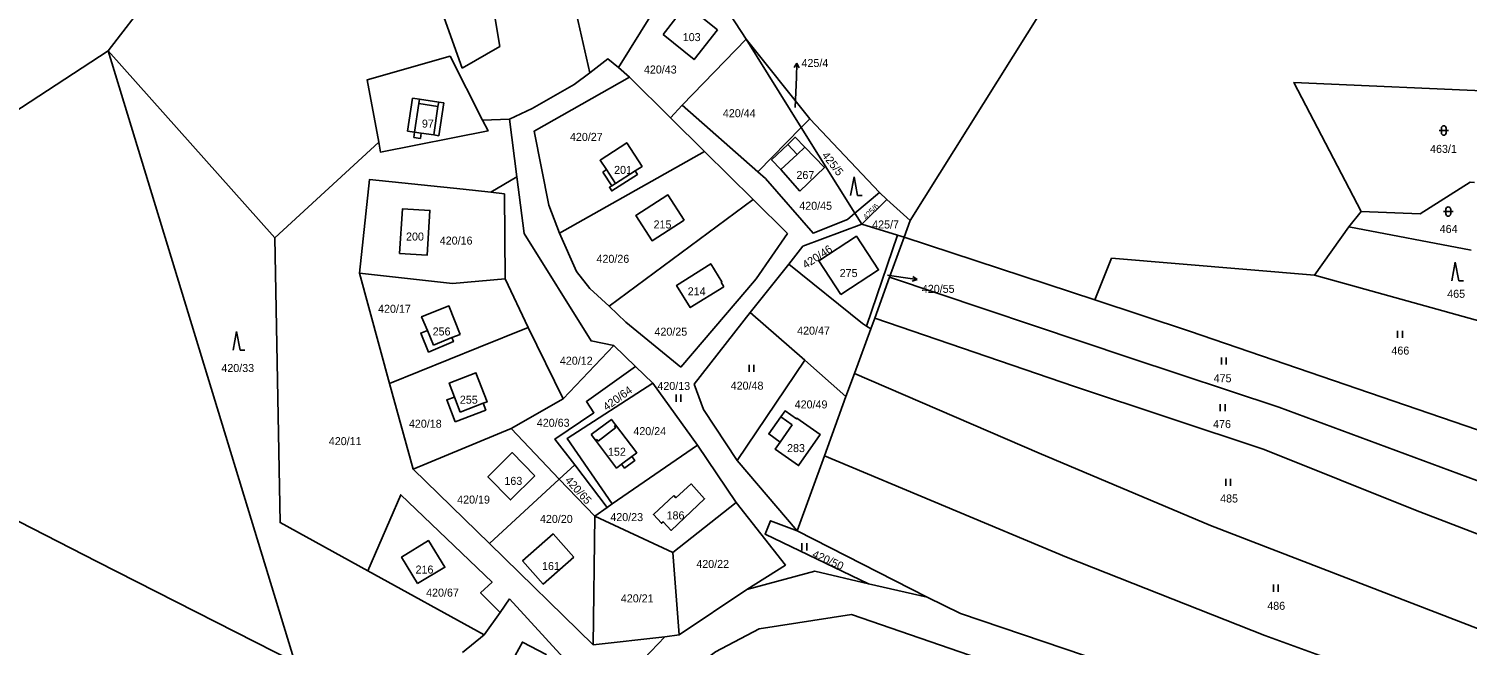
# Model space of a CAD drawing. Extents: x -751333 to -746055, y -1133395 to -1129777.
# Drawn here: x -748944.8 to -748639.3, y -1130557.3 to -1130426.4 of the extents above; entities that cross this region are included whole.
import ezdxf

# ---------------------------------------------------------------- set-up
doc = ezdxf.new("R2010")
doc.units = 0
for name, color, linetype in [('Hranice parcel', 7, 'Continuous'), ('Parcelní čísla', 7, 'Continuous'), ('Pop  PČ popisy', 7, 'Continuous'), ('Vnitřní kresba', 7, 'Continuous'), ('Značky kultur', 7, 'Continuous')]:
    doc.layers.add(name, color=color, linetype=linetype)

msp = doc.modelspace()

# ---------------------------------------------------------------- linework, layer by layer
at = {"layer": 'Hranice parcel'}
for p, q in [((-748902.2, -1130397.64), (-748927.95, -1130431.02)), ((-748849.48, -1130401.7), (-748844.76, -1130430.14)), ((-748819.51, -1130434.58), (-748804.37, -1130410.14)), ((-748792.44, -1130428.53), (-748804.37, -1130410.14)), ((-748805.98, -1130442.59), (-748792.44, -1130428.53)), ((-748778.89, -1130445.44), (-748792.44, -1130428.53)), ((-748780.72, -1130447.3), (-748792.44, -1130428.53)), ((-748927.95, -1130431.02), (-748892.55, -1130470.72)), ((-748927.95, -1130431.02), (-748888.26, -1130560.86)), ((-748844.76, -1130430.14), (-748852.71, -1130434.75)), ((-748817.21, -1130436.65), (-748819.51, -1130434.58)), ((-748808.51, -1130445.24), (-748817.21, -1130436.65)), ((-748805.98, -1130442.59), (-748808.51, -1130445.24)), ((-748789.95, -1130456.7), (-748805.98, -1130442.59)), ((-748848.41, -1130445.73), (-748842.67, -1130445.58)), ((-748841.12, -1130457.78), (-748842.67, -1130445.58)), ((-748801.29, -1130452.44), (-748808.51, -1130445.24)), ((-748789.95, -1130456.7), (-748780.72, -1130447.3)), ((-748780.72, -1130447.3), (-748778.89, -1130445.44)), ((-748769.34, -1130465.53), (-748780.72, -1130447.3)), ((-748764.11, -1130461.14), (-748778.89, -1130445.44)), ((-748892.55, -1130470.72), (-748870.46, -1130450.45)), ((-748832.08, -1130469.75), (-748801.29, -1130452.44)), ((-748801.29, -1130452.44), (-748790.91, -1130462.62)), ((-748788.31, -1130458.17), (-748789.95, -1130456.7)), ((-748852.5, -1130460.44), (-748846.67, -1130461.06)), ((-748846.67, -1130461.06), (-748841.12, -1130457.78)), ((-748839.58, -1130469.86), (-748841.12, -1130457.78)), ((-748846.67, -1130461.06), (-748843.74, -1130461.37)), ((-748843.74, -1130461.37), (-748843.6, -1130479.46)), ((-748790.91, -1130462.62), (-748821.52, -1130485.28)), ((-748790.91, -1130462.62), (-748783.62, -1130469.82)), ((-748769.34, -1130465.53), (-748764.11, -1130461.14)), ((-748767.88, -1130467.87), (-748762.56, -1130462.59)), ((-748762.56, -1130462.59), (-748764.11, -1130461.14)), ((-748757.6, -1130467.05), (-748762.56, -1130462.59)), ((-748769.34, -1130465.53), (-748770.9, -1130466.83)), ((-748767.88, -1130467.87), (-748769.34, -1130465.53)), ((-748664.43, -1130468.41), (-748661.8, -1130465.15)), ((-748760.27, -1130470.2), (-748767.88, -1130467.87)), ((-748757.6, -1130467.05), (-748758.89, -1130470.62)), ((-748671.7, -1130478.68), (-748664.43, -1130468.41)), ((-748664.43, -1130468.41), (-748638.43, -1130473.4)), ((-748766.84, -1130489.51), (-748760.27, -1130470.2)), ((-748761.98, -1130479.13), (-748758.89, -1130470.62)), ((-748758.89, -1130470.62), (-748760.27, -1130470.2)), ((-748758.89, -1130470.62), (-748718.34, -1130483.88)), ((-748868.14, -1130501.65), (-748874.54, -1130478.26)), ((-748791.56, -1130486.57), (-748783.35, -1130476.32)), ((-748843.6, -1130479.46), (-748838.72, -1130489.81)), ((-748797.15, -1130481.13), (-748797.74, -1130480.18)), ((-748765.12, -1130487.78), (-748761.98, -1130479.13)), ((-748803.45, -1130501.81), (-748791.56, -1130486.57)), ((-748791.56, -1130486.57), (-748779.98, -1130496.71)), ((-748765.94, -1130490.05), (-748765.12, -1130487.78)), ((-748838.72, -1130489.81), (-748831.25, -1130504.91)), ((-748769.41, -1130499.53), (-748765.94, -1130490.05)), ((-748765.94, -1130490.05), (-748766.84, -1130489.51)), ((-748831.25, -1130504.91), (-748820.54, -1130493.62)), ((-748820.54, -1130493.62), (-748815.91, -1130498.09)), ((-748779.98, -1130496.71), (-748794.31, -1130518)), ((-748771.22, -1130504.47), (-748779.98, -1130496.71)), ((-748815.91, -1130498.09), (-748812.25, -1130501.61)), ((-748771.22, -1130504.47), (-748769.41, -1130499.53)), ((-748863.15, -1130519.89), (-748868.14, -1130501.65)), ((-748812.25, -1130501.61), (-748802.76, -1130514.74)), ((-748831.25, -1130504.91), (-748842.3, -1130511.21)), ((-748775.79, -1130517.06), (-748771.22, -1130504.47)), ((-748842.3, -1130511.21), (-748863.15, -1130519.89)), ((-748832.1, -1130521.99), (-748842.3, -1130511.21)), ((-748802.76, -1130514.74), (-748820.87, -1130527.26)), ((-748802.76, -1130514.74), (-748794.57, -1130526.92)), ((-748794.31, -1130518), (-748781.55, -1130532.95)), ((-748781.55, -1130532.95), (-748775.79, -1130517.06)), ((-748846.93, -1130535.69), (-748863.15, -1130519.89)), ((-748832.1, -1130521.99), (-748828.83, -1130518.95)), ((-748828.83, -1130518.95), (-748821.95, -1130528)), ((-748846.93, -1130535.69), (-748832.1, -1130521.99)), ((-748824.58, -1130529.82), (-748832.1, -1130521.99)), ((-748820.87, -1130527.26), (-748821.95, -1130528)), ((-748794.57, -1130526.92), (-748807.97, -1130537.59)), ((-748824.94, -1130557.15), (-748824.58, -1130529.82)), ((-748821.95, -1130528), (-748824.58, -1130529.82)), ((-748807.97, -1130537.59), (-748824.58, -1130529.82)), ((-748754, -1130547.08), (-748781.55, -1130532.95)), ((-748824.94, -1130557.15), (-748846.93, -1130535.69)), ((-748806.63, -1130555.06), (-748807.97, -1130537.59)), ((-748848.06, -1130555.08), (-748872.79, -1130541.46)), ((-748806.63, -1130555.06), (-748792.29, -1130545.43)), ((-748766.4, -1130544.2), (-748754, -1130547.08)), ((-748842.68, -1130547.42), (-748844.69, -1130550.29)), ((-748822.02, -1130569.92), (-748842.68, -1130547.42)), ((-748844.69, -1130550.29), (-748848.06, -1130555.08)), ((-748848.06, -1130555.08), (-748852.67, -1130558.78)), ((-748809.68, -1130555.47), (-748806.63, -1130555.06)), ((-748809.68, -1130555.47), (-748824.94, -1130557.15))]:
    msp.add_line(p, q, dxfattribs=at)
for points in [[(-748668.63, -1130323.88), (-748723.49, -1130412.55), (-748757.6, -1130467.05)], [(-748825.64, -1130435.7), (-748830.6, -1130413.85), (-748827.29, -1130401.09), (-748824.29, -1130394.55), (-748817.71, -1130391.16)], [(-748852.71, -1130434.75), (-748864.73, -1130401.17), (-748858.73, -1130399.01)], [(-748798.53, -1130426.57), (-748805.14, -1130421.28), (-748810.06, -1130427.6)], [(-748810.06, -1130427.6), (-748803.47, -1130432.9), (-748798.53, -1130426.57)], [(-749070.43, -1130467.11), (-748982.99, -1130466.97), (-748927.95, -1130431.02)], [(-748848.41, -1130445.73), (-748855.31, -1130432.18), (-748872.92, -1130437.22), (-748870.46, -1130450.45)], [(-748825.64, -1130435.7), (-748821.76, -1130432.75), (-748819.51, -1130434.58)], [(-748842.67, -1130445.58), (-748837.83, -1130443.26), (-748828.93, -1130438.2), (-748825.64, -1130435.7)], [(-748817.21, -1130436.65), (-748837.42, -1130448.09), (-748834.32, -1130463.8), (-748832.08, -1130469.75)], [(-748661.8, -1130465.15), (-748676.09, -1130437.74), (-748631.31, -1130439.73)], [(-748870.46, -1130450.45), (-748870.08, -1130452.52), (-748847.24, -1130448.03), (-748848.41, -1130445.73)], [(-748822.89, -1130456.78), (-748820.97, -1130459.7), (-748821.47, -1130460.02), (-748820.98, -1130460.78), (-748815.5, -1130457.27), (-748815.97, -1130456.53), (-748814.52, -1130455.58), (-748817.78, -1130450.55), (-748823.43, -1130454.26), (-748822.1, -1130456.26), (-748822.89, -1130456.78)], [(-748781, -1130460.83), (-748775.78, -1130455.82), (-748779.97, -1130451.47), (-748781.98, -1130449.37), (-748783.6, -1130450.93), (-748787.01, -1130454.2), (-748785.04, -1130456.25), (-748781, -1130460.83)], [(-748874.54, -1130478.26), (-748872.39, -1130458.34), (-748852.5, -1130460.44)], [(-748770.9, -1130466.83), (-748778.22, -1130469.78), (-748788.31, -1130458.17)], [(-748661.8, -1130465.15), (-748649.27, -1130465.67), (-748638.63, -1130458.96), (-748637.75, -1130459.01)], [(-748805.57, -1130466.96), (-748809.03, -1130461.64), (-748815.82, -1130465.97), (-748812.39, -1130471.35), (-748805.57, -1130466.96)], [(-748866.07, -1130474.04), (-748860.16, -1130474.4), (-748859.58, -1130464.94), (-748865.44, -1130464.59), (-748866.07, -1130474.04)], [(-749070.43, -1130467.11), (-749012.81, -1130497.2), (-748930.34, -1130539.46), (-748888.26, -1130560.86)], [(-748783.35, -1130476.32), (-748780.36, -1130472.52), (-748767.88, -1130467.87)], [(-748892.55, -1130470.72), (-748891.42, -1130531.21), (-748872.79, -1130541.46)], [(-748820.54, -1130493.62), (-748825.34, -1130492.64), (-748839.58, -1130469.86)], [(-748821.52, -1130485.28), (-748825.63, -1130481.5), (-748828.48, -1130477.93), (-748832.08, -1130469.75)], [(-748783.62, -1130469.82), (-748790.29, -1130479.46), (-748792.26, -1130481.76), (-748806.27, -1130498.24)], [(-748772.28, -1130482.78), (-748764.3, -1130477.55), (-748768.99, -1130470.4), (-748776.95, -1130475.63), (-748772.28, -1130482.78)], [(-748718.34, -1130483.88), (-748714.81, -1130475.07), (-748671.7, -1130478.68)], [(-748874.54, -1130478.26), (-748854.82, -1130480.43), (-748843.6, -1130479.46)], [(-748797.74, -1130480.18), (-748797.55, -1130480.06), (-748799.94, -1130476.26), (-748807.21, -1130480.86), (-748804.28, -1130485.57), (-748797.15, -1130481.13)], [(-748783.35, -1130476.32), (-748767.74, -1130488.96), (-748766.84, -1130489.51)], [(-748671.7, -1130478.68), (-748633.74, -1130489.24), (-748618.21, -1130483.5)], [(-748761.98, -1130479.13), (-748710.91, -1130496.25), (-748679.26, -1130506.7), (-748621.93, -1130527.97)], [(-748718.34, -1130483.88), (-748698.29, -1130490.59), (-748629.43, -1130514.15)], [(-748853.13, -1130491.26), (-748855.56, -1130485.21), (-748861.36, -1130487.49), (-748860.13, -1130490.42), (-748861.54, -1130490.99), (-748859.85, -1130495.02), (-748854.59, -1130492.79), (-748854.96, -1130491.92), (-748853.13, -1130491.26)], [(-748806.27, -1130498.24), (-748817.98, -1130488.65), (-748821.52, -1130485.28)], [(-748765.12, -1130487.78), (-748722.68, -1130502.34), (-748682.4, -1130515.73), (-748650.26, -1130528.57), (-748607.86, -1130544.88)], [(-748868.14, -1130501.65), (-748849.28, -1130494.06), (-748838.72, -1130489.81)], [(-748854.2, -1130509.79), (-748847.71, -1130507.33), (-748848.25, -1130505.89), (-748847.44, -1130505.58), (-748849.81, -1130499.38), (-748855.49, -1130501.59), (-748854.37, -1130504.59), (-748856.01, -1130505.15), (-748854.2, -1130509.79)], [(-748828.83, -1130518.95), (-748833.02, -1130513.48), (-748824.76, -1130507.89), (-748826.36, -1130505.51), (-748815.91, -1130498.09)], [(-748769.41, -1130499.53), (-748730.21, -1130516.5), (-748693.83, -1130531.8), (-748627.18, -1130557.56), (-748603.84, -1130566.17), (-748577.63, -1130576.56)], [(-748812.25, -1130501.61), (-748830.46, -1130513.37), (-748820.87, -1130527.26)], [(-748794.31, -1130518), (-748801.5, -1130507.17), (-748803.45, -1130501.81)], [(-748816.7, -1130517.18), (-748815.67, -1130516.4), (-748820.14, -1130510.48), (-748821.04, -1130509.29), (-748825.32, -1130512.52)], [(-748785.03, -1130508.74), (-748784.15, -1130507.49), (-748781.75, -1130509.19), (-748781.63, -1130509.04), (-748776.67, -1130512.52), (-748781.3, -1130519.11), (-748786.27, -1130515.61), (-748785.21, -1130514.11), (-748787.62, -1130512.4), (-748785.03, -1130508.74)], [(-748825.32, -1130512.52), (-748824.39, -1130513.73), (-748819.95, -1130519.63), (-748818.86, -1130518.81), (-748818.22, -1130519.65), (-748816.06, -1130518.02), (-748816.7, -1130517.18)], [(-748837.33, -1130521.27), (-748842.14, -1130516.36), (-748847.28, -1130521.51), (-748842.48, -1130526.4), (-748837.33, -1130521.27)], [(-748775.79, -1130517.06), (-748724.37, -1130538.57), (-748682.28, -1130555.19), (-748652.69, -1130565.92), (-748602.7, -1130584.94), (-748579.32, -1130593.13)], [(-748807.77, -1130525.47), (-748812.13, -1130529.47), (-748810.42, -1130531.37), (-748810.07, -1130531.04), (-748808.34, -1130532.87), (-748801.24, -1130526.14), (-748804.12, -1130523), (-748807.33, -1130525.95), (-748807.77, -1130525.47)], [(-748872.79, -1130541.46), (-748865.77, -1130525.3), (-748846.38, -1130543.87), (-748848.82, -1130546.16), (-748844.69, -1130550.29)], [(-748794.57, -1130526.92), (-748784.09, -1130540.23), (-748792.29, -1130545.43)], [(-748829.04, -1130538.57), (-748833.41, -1130533.62), (-748839.91, -1130539.35), (-748835.51, -1130544.26), (-748829.04, -1130538.57)], [(-748766.4, -1130544.2), (-748788.4, -1130533.64), (-748787.24, -1130530.81), (-748781.55, -1130532.95)], [(-748862.21, -1130544.17), (-748856.41, -1130540.69), (-748859.91, -1130535.03), (-748865.59, -1130538.53), (-748862.21, -1130544.17)], [(-748792.29, -1130545.43), (-748777.8, -1130541.55), (-748766.4, -1130544.2)], [(-748694.25, -1130568.39), (-748746.89, -1130550.49), (-748754, -1130547.08)], [(-748671.54, -1130609.27), (-748689.21, -1130588.28), (-748698.85, -1130579.03), (-748711.73, -1130570.87), (-748770.07, -1130550.7), (-748789.66, -1130553.8), (-748798.91, -1130558.69), (-748806.83, -1130564.57), (-748827.25, -1130594.48)], [(-748843.04, -1130562.3), (-748837.93, -1130565), (-748834.89, -1130559.25), (-748839.93, -1130556.59), (-748843.04, -1130562.3)], [(-748822.02, -1130569.92), (-748818.59, -1130564.8), (-748809.68, -1130555.47)]]:
    msp.add_lwpolyline(points, dxfattribs=at)
at = {"layer": 'Pop  PČ popisy'}
for p, q in [((-748781.655, -1130433.621), (-748782.191, -1130434.604)), ((-748781.76, -1130436.62), (-748781.655, -1130433.621)), ((-748781.655, -1130433.621), (-748781.19, -1130434.639)), ((-748781.98, -1130443.1), (-748781.76, -1130436.62)), ((-748762.38, -1130478.64), (-748759.07, -1130479.14)), ((-748759.07, -1130479.14), (-748756.106, -1130479.609)), ((-748756.106, -1130479.609), (-748757.173, -1130479.947)), ((-748756.106, -1130479.609), (-748757.017, -1130478.958))]:
    msp.add_line(p, q, dxfattribs=at)
at = {"layer": 'Vnitřní kresba'}
for p, q in [((-748864.32, -1130448.09), (-748863.29, -1130441.1)), ((-748861.79, -1130441.32), (-748863.29, -1130441.1)), ((-748861.79, -1130441.32), (-748861.93, -1130442.25)), ((-748857.7, -1130441.93), (-748861.79, -1130441.32)), ((-748857.89, -1130442.87), (-748857.7, -1130441.93)), ((-748856.66, -1130442.08), (-748857.7, -1130441.93)), ((-748857.69, -1130449.07), (-748856.66, -1130442.08)), ((-748861.93, -1130442.25), (-748862.83, -1130448.3)), ((-748861.93, -1130442.25), (-748857.89, -1130442.87)), ((-748858.72, -1130448.9), (-748857.89, -1130442.87)), ((-748862.83, -1130448.3), (-748864.32, -1130448.09)), ((-748863, -1130449.44), (-748862.83, -1130448.3)), ((-748863, -1130449.44), (-748861.6, -1130449.68)), ((-748862.83, -1130448.3), (-748861.43, -1130448.51)), ((-748861.43, -1130448.51), (-748861.6, -1130449.68)), ((-748858.72, -1130448.9), (-748861.43, -1130448.51)), ((-748857.69, -1130449.07), (-748858.72, -1130448.9)), ((-748783.6, -1130450.93), (-748781.59, -1130453.02)), ((-748781.59, -1130453.02), (-748785.04, -1130456.25)), ((-748781.59, -1130453.02), (-748779.97, -1130451.47)), ((-748822.1, -1130456.26), (-748820.16, -1130459.19)), ((-748820.16, -1130459.19), (-748815.97, -1130456.53)), ((-748820.97, -1130459.7), (-748820.16, -1130459.19)), ((-748860.13, -1130490.42), (-748858.82, -1130493.54)), ((-748858.82, -1130493.54), (-748854.96, -1130491.92)), ((-748853.18, -1130507.76), (-748854.37, -1130504.59)), ((-748853.18, -1130507.76), (-748848.25, -1130505.89)), ((-748785.03, -1130508.74), (-748782.61, -1130510.45)), ((-748820.09, -1130511.05), (-748823.86, -1130513.93)), ((-748820.14, -1130510.48), (-748820.38, -1130510.66)), ((-748820.38, -1130510.66), (-748820.09, -1130511.05)), ((-748782.61, -1130510.45), (-748785.21, -1130514.11)), ((-748824.15, -1130513.55), (-748824.39, -1130513.73)), ((-748823.86, -1130513.93), (-748824.15, -1130513.55)), ((-748816.7, -1130517.18), (-748818.86, -1130518.81))]:
    msp.add_line(p, q, dxfattribs=at)
at = {"layer": 'Značky kultur'}
for p, q in [((-748645.251, -1130447.951), (-748643.249, -1130447.951)), ((-748644.751, -1130447.451), (-748644.751, -1130448.452)), ((-748643.749, -1130448.452), (-748643.749, -1130447.451)), ((-748769.49, -1130457.79), (-748770.24, -1130461.79)), ((-748768.74, -1130461.79), (-748769.49, -1130457.79)), ((-748768.74, -1130461.79), (-748767.744, -1130461.79)), ((-748644.291, -1130465.161), (-748642.289, -1130465.161)), ((-748643.791, -1130464.661), (-748643.791, -1130465.662)), ((-748642.789, -1130465.662), (-748642.789, -1130464.661)), ((-748641.81, -1130475.88), (-748642.56, -1130479.88)), ((-748641.06, -1130479.88), (-748641.81, -1130475.88)), ((-748641.06, -1130479.88), (-748640.064, -1130479.88)), ((-748900.64, -1130490.63), (-748901.39, -1130494.63)), ((-748899.89, -1130494.63), (-748900.64, -1130490.63)), ((-748654.051, -1130491.99), (-748654.051, -1130490.49)), ((-748653.05, -1130491.99), (-748653.05, -1130490.49)), ((-748899.89, -1130494.63), (-748898.894, -1130494.63)), ((-748691.451, -1130497.67), (-748691.451, -1130496.17)), ((-748690.45, -1130497.67), (-748690.45, -1130496.17)), ((-748791.811, -1130499.23), (-748791.811, -1130497.73)), ((-748790.81, -1130499.23), (-748790.81, -1130497.73)), ((-748807.291, -1130505.55), (-748807.291, -1130504.05)), ((-748806.29, -1130505.55), (-748806.29, -1130504.05)), ((-748691.711, -1130507.54), (-748691.711, -1130506.04)), ((-748690.71, -1130507.54), (-748690.71, -1130506.04)), ((-748690.521, -1130523.4), (-748690.521, -1130521.9)), ((-748689.52, -1130523.4), (-748689.52, -1130521.9)), ((-748780.561, -1130537.12), (-748780.561, -1130535.62)), ((-748779.56, -1130537.12), (-748779.56, -1130535.62)), ((-748680.401, -1130545.89), (-748680.401, -1130544.39)), ((-748679.4, -1130545.89), (-748679.4, -1130544.39))]:
    msp.add_line(p, q, dxfattribs=at)
for centre, start, end in [((-748644.25, -1130447.451), 0, 180), ((-748644.25, -1130448.451), 180, 359.98789), ((-748643.29, -1130464.661), 0, 180), ((-748643.29, -1130465.661), 180, 359.98789)]:
    msp.add_arc(centre, 0.5, start, end, dxfattribs=at)

# ---------------------------------------------------------------- texts
at = {"layer": 'Parcelní čísla'}
for s, p in [('103', (-748805.88, -1130428.97)), ('425/4', (-748780.66, -1130434.47)), ('420/43', (-748814.13, -1130435.85)), ('420/44', (-748797.36, -1130445.13)), ('97', (-748861.28, -1130447.34)), ('420/27', (-748829.84, -1130450.16)), ('463/1', (-748647.16, -1130452.71)), ('201', (-748820.46, -1130457.17)), ('267', (-748781.74, -1130458.25)), ('420/45', (-748781.13, -1130464.79)), ('200', (-748864.65, -1130471.32)), ('215', (-748812.08, -1130468.75)), ('425/7', (-748765.65, -1130468.76)), ('464', (-748645.12, -1130469.71)), ('420/16', (-748857.487, -1130472.18)), ('420/26', (-748824.2, -1130476.05)), ('275', (-748772.56, -1130479.08)), ('214', (-748804.835, -1130482.96)), ('420/55', (-748755.1, -1130482.428)), ('465', (-748643.52, -1130483.48)), ('420/17', (-748870.59, -1130486.66)), ('256', (-748859, -1130491.48)), ('420/25', (-748811.89, -1130491.52)), ('420/47', (-748781.59, -1130491.3)), ('466', (-748655.37, -1130495.54)), ('420/12', (-748831.977, -1130497.69)), ('420/33', (-748903.87, -1130499.24)), ('475', (-748693.13, -1130501.42)), ('420/13', (-748811.27, -1130503.05)), ('420/48', (-748795.7, -1130502.98)), ('255', (-748853.22, -1130505.97)), ('420/49', (-748782.11, -1130506.97)), ('420/18', (-748864.04, -1130511.07)), ('420/63', (-748836.877, -1130510.87)), ('420/24', (-748816.37, -1130512.65)), ('476', (-748693.25, -1130511.15)), ('420/11', (-748881.05, -1130514.77)), ('152', (-748821.76, -1130517.02)), ('283', (-748783.725, -1130516.25)), ('163', (-748843.76, -1130523.21)), ('420/19', (-748853.79, -1130527.18)), ('485', (-748691.75, -1130526.95)), ('420/20', (-748836.21, -1130531.29)), ('420/23', (-748821.26, -1130530.9)), ('186', (-748809.315, -1130530.54)), ('161', (-748835.77, -1130541.29)), ('420/22', (-748803, -1130540.85)), ('216', (-748862.63, -1130542.04)), ('420/67', (-748860.387, -1130546.94)), ('420/21', (-748819.03, -1130548.16)), ('486', (-748681.74, -1130549.74))]:
    msp.add_text(s, height=1.7, dxfattribs=at).set_placement(p)
for s, height, rotation, p in [('425/5', 1.7, 308, (-748776.439, -1130453.273)), ('425/6', 1.14, 45, (-748766.901, -1130466.937)), ('420/46', 1.7, 33, (-748779.767, -1130477.362)), ('420/64', 1.7, 36, (-748822.054, -1130507.548)), ('420/65', 1.7, 312, (-748831.003, -1130522.335)), ('420/50', 1.7, 336, (-748778.545, -1130538.526))]:
    msp.add_text(s, height=height, rotation=rotation, dxfattribs=at).set_placement(p)

doc.saveas('drawing.dxf')
